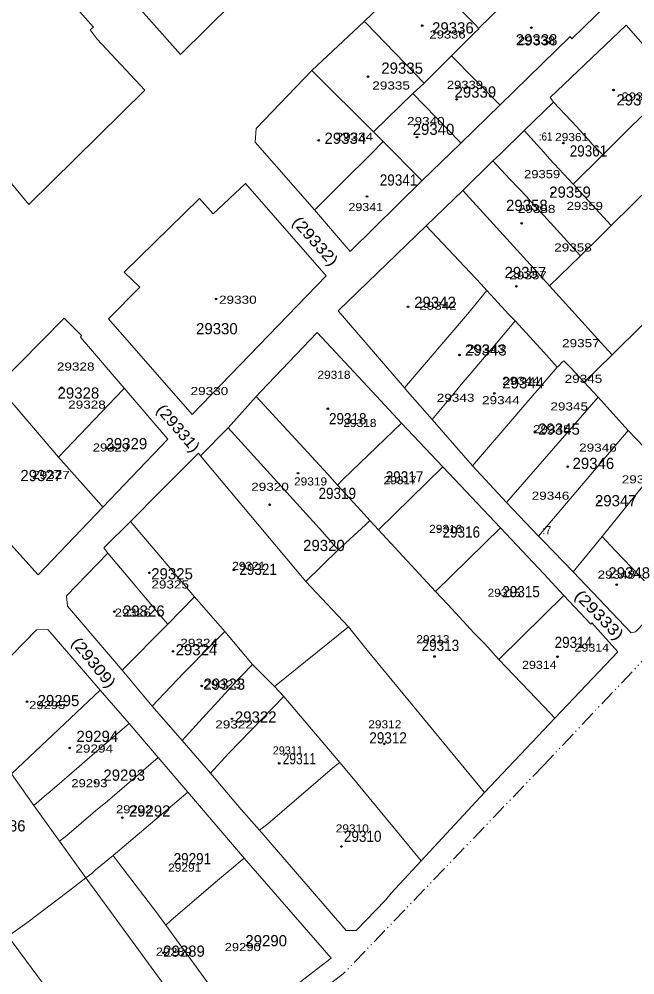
# Model space of a CAD drawing. Extents: x 650553 to 652508, y 239277 to 241647.
# Drawn here: x 650831.5 to 651029.3, y 239562.7 to 239869.5 of the extents above; entities that cross this region are included whole.
import ezdxf

# ---------------------------------------------------------------- set-up
doc = ezdxf.new("R2010")
doc.units = 0
doc.header["$PDMODE"] = 32
doc.header["$PDSIZE"] = 0.5
doc.linetypes.add('DASH_DOUBLE_DOT', pattern=[9.2, 5, -1.2, 0.3, -1.2, 0.3, -1.2])
for name, color, linetype in [('19', 7, 'Continuous'), ('20', 7, 'Continuous'), ('6', 7, 'Continuous')]:
    doc.layers.add(name, color=color, linetype=linetype)
for name, color, linetype, lineweight in [('3', 7, 'Continuous', 13), ('5', 7, 'Continuous', 13), ('52', 7, 'DASH_DOUBLE_DOT', 13)]:
    doc.layers.add(name, color=color, linetype=linetype, lineweight=lineweight)

msp = doc.modelspace()

# ---------------------------------------------------------------- linework, layer by layer
at = {"layer": '3'}
for p, q in [((650879.03, 239720.07), (650877, 239718.08)), ((650949.15, 239586.69), (650951.05, 239588.9))]:
    msp.add_line(p, q, dxfattribs=at)
for points in [[(650908.41, 239883.02), (650883.34, 239858.18), (650864.77, 239879.28), (650855.55, 239889.77), (650845.58, 239901.42), (650836.36, 239911.69), (650810.07, 239942.07), (650801.92, 239951.45), (650792.87, 239961.83), (650784.09, 239971.6), (650771.89, 239986.02)], [(650758.53, 239902.67), (650765.192, 239907.872), (650764.516, 239908.49), (650788.613, 239929.179), (650789.086, 239928.488), (650795.35, 239933.7), (650797.42, 239931.11), (650799.14, 239932.39), (650804.99, 239925.16), (650803.46, 239923.73), (650817.53, 239907.6), (650818.21, 239908.05), (650821.441, 239904.446), (650826.146, 239908.699), (650835.897, 239897.399), (650830.96, 239893.24), (650834.46, 239889.42), (650833.85, 239888.76), (650847.66, 239872.31), (650849.29, 239873.74), (650855.37, 239866.92), (650854.34, 239866.07), (650856.61, 239863.11), (650871.916, 239846.694)], [(650926.38, 239808.25), (650907.36, 239830.06), (650907.67, 239834.39), (650925.58, 239852.98), (650942.36, 239868.78), (650960.13, 239885.88), (650986.44, 239912.2)], [(650758.53, 239902.67), (650760.73, 239900.19), (650759.19, 239898.72), (650765.32, 239891.73), (650766.99, 239892.99), (650780.49, 239876.39), (650779.94, 239875.79), (650783.12, 239871.78), (650778.188, 239867.604), (650787.995, 239856.292), (650792.37, 239860.72), (650795.54, 239856.63), (650796.29, 239857.11), (650810.17, 239840.72), (650808.48, 239839.35), (650814.17, 239832.2), (650815.19, 239833.07), (650817.72, 239830.34), (650834.635, 239810.007), (650871.916, 239846.694)], [(651004.77, 239891.58), (651020.46, 239874.33), (651009.06, 239863.21), (651008.47, 239863.96), (650986.02, 239841.96), (650973.43, 239829.74), (650960.91, 239817.58), (650937.89, 239794.94), (650926.38, 239808.25)], [(651000, 239839.83), (651003.18, 239842.9), (651002.08, 239844.3), (651026.48, 239867.54), (651042.7, 239849.13), (651054.6, 239835.68), (651074.89, 239813.04), (651087.13, 239799.56), (651095.02, 239790.72), (651117.9, 239765.17), (651103.31, 239750)], [(651000, 239839.83), (650993.74, 239833.78), (650985.86, 239826.07), (650983.65, 239824.03), (650974, 239814.51), (650962.27, 239803.17), (650934.01, 239775.82)], [(650887.09, 239742.6), (650860.21, 239773.29), (650870.256, 239783.469), (650865.276, 239788.29), (650889.499, 239811.936), (650893.871, 239806.992), (650904.24, 239816.76)], [(650904.24, 239816.76), (650930.11, 239787.09), (650887.09, 239742.6)], [(650934.01, 239775.82), (650955.34, 239751.1), (650956.3, 239750)], [(650824.49, 239751.82), (650845.96, 239773.46), (650851.58, 239767.89), (650851.19, 239767.43), (650865.28, 239751.04), (650879.32, 239734.62), (650858.42, 239712.84)], [(650909.2, 239750), (650927.26, 239768.94), (650944.87, 239750)], [(650909.2, 239750), (650907.66, 239748.38), (650898.71, 239738.31), (650889.76, 239729.33), (650889.14, 239730.16), (650879.03, 239720.07)], [(650944.87, 239750), (650954.33, 239739.84), (650967.57, 239725.8), (650986.1, 239706.21), (651000, 239691.42)], [(650956.3, 239750), (650964.17, 239740.93), (650977.18, 239726.11), (650988.08, 239714.35), (650998.38, 239703.47), (651000, 239701.81)], [(651000, 239701.81), (651009.47, 239692.08), (651028.09, 239672.47), (651029.48, 239672.78), (651038.83, 239682.45), (651058.85, 239703.52), (651067.38, 239712.72), (651077.17, 239722.24), (651096.93, 239743.36), (651103.31, 239750)], [(650858.42, 239712.84), (650837.68, 239691.06), (650802.53, 239729.93)], [(650877, 239718.08), (650867.3, 239708.18), (650858.75, 239699.74), (650860.04, 239698.11), (650846.76, 239684.39), (650847.07, 239681), (650864.66, 239660.49), (650874.22, 239648.99), (650883.85, 239637.97), (650893, 239627.41), (650902.79, 239615.77), (650908.76, 239609.09), (650936.55, 239576.94), (650939.8, 239576.9), (650949.15, 239586.69)], [(651000, 239691.42), (651006.48, 239684.52), (651015.11, 239675.28), (651015.45, 239675.69), (651023.78, 239666.38), (651003.54, 239645.12), (651000, 239641.38)], [(650766.66, 239555.85), (650762.69, 239561.36), (650746.99, 239583.49), (650766.57, 239599.63), (650765.87, 239600.32), (650777.65, 239613.61), (650778.65, 239612.38), (650790.25, 239624.22), (650813.28, 239649.12), (650837.06, 239673.5), (650840.71, 239673.57), (650857.5, 239654.04), (650866.83, 239643.35), (650876.22, 239632.41), (650885.67, 239621.34), (650903.75, 239600.18), (650931.7, 239568.01), (650902.59, 239545.65), (650893.39, 239538.45), (650868.88, 239519.76), (650843.34, 239500)], [(650951.05, 239588.9), (650960.64, 239599.28), (650980.94, 239621.22), (651000, 239641.38)]]:
    msp.add_lwpolyline(points, dxfattribs=at)
at = {"layer": '5'}
for p, q in [((650993.74, 239833.78), (651000, 239826.77)), ((651009.43, 239816.56), (651018.95, 239825.92)), ((650974, 239814.51), (651000, 239785.87)), ((651000, 239806.45), (651011.83, 239793.51)), ((651000, 239762.54), (651004.33, 239757.8)), ((650971.69, 239750), (650964.17, 239740.93)), ((650988.08, 239714.35), (651017.51, 239748.19)), ((650998.38, 239703.47), (651027.12, 239737.39)), ((650967.57, 239725.8), (650946.94, 239705.52)), ((650986.1, 239706.21), (650965.25, 239685.71)), ((651000, 239678.11), (651006.48, 239684.52)), ((650985.64, 239663.92), (651000, 239678.11)), ((650937.33, 239674.4), (650913.52, 239655.26)), ((650857.5, 239654.04), (650829.08, 239627.18)), ((651000, 239648.84), (651003.54, 239645.12))]:
    msp.add_line(p, q, dxfattribs=at)
for points in [[(651000, 239886.91), (650979.43, 239866.78), (650979.19, 239866.43), (650977.59, 239864.89), (650976.17, 239863.49), (650970.39, 239857.73), (650961.58, 239849), (650957.95, 239845.67), (650945.33, 239833.29)], [(650960.13, 239885.88), (650960.617, 239885.38), (650968.98, 239876.79), (650975.37, 239870.37), (650978.06, 239867.64), (650979.19, 239866.43)], [(650942.36, 239868.78), (650942.846, 239868.28), (650961.58, 239849)], [(650970.39, 239857.73), (650985.524, 239842.46), (650986.02, 239841.96)], [(650925.58, 239852.98), (650926.08, 239852.482), (650945.33, 239833.29), (650948.48, 239830.21)], [(651003.18, 239842.9), (651010.69, 239834.98), (651015.18, 239829.88), (651015.37, 239829.53), (651018.95, 239825.92), (651028.04, 239834.93), (651033.56, 239840.23), (651042.7, 239849.13)], [(650957.95, 239845.67), (650972.944, 239830.24), (650973.43, 239829.74)], [(651001.83, 239783.86), (651011.83, 239793.51), (651018.25, 239799.79), (651021.7, 239803.27), (651054.6, 239835.68)], [(650948.48, 239830.21), (650944.86, 239826.59), (650935.08, 239816.87)], [(650948.48, 239830.21), (650960.418, 239818.08), (650960.91, 239817.58)], [(651000, 239826.77), (651001.89, 239824.65), (651009.43, 239816.56), (651021.7, 239803.27)], [(650983.65, 239824.03), (650989.15, 239818.18), (650994.73, 239812.37), (650994.92, 239812.08), (650999.38, 239807.13), (651000, 239806.45)], [(650935.08, 239816.87), (650926.88, 239808.745), (650926.38, 239808.25)], [(651012.96, 239753.01), (651021.99, 239761.78), (651031.72, 239771.33), (651041.21, 239780.58), (651044.83, 239784.08), (651056.34, 239795.18), (651074.89, 239813.04)], [(650962.27, 239803.17), (650979.93, 239784.39), (650981.77, 239782.39), (650988.83, 239774.73), (650990.79, 239772.63), (651000, 239762.54)], [(651000, 239785.87), (651001.83, 239783.86), (651018.46, 239765.63), (651021.99, 239761.78)], [(650981.77, 239782.39), (650975.54, 239774.82), (650955.34, 239751.1)], [(650990.79, 239772.63), (650987.18, 239768.25), (650972.99, 239751.57), (650971.69, 239750)], [(650977.18, 239726.11), (651004.33, 239757.8), (651004.79, 239758.09), (651005.89, 239759.37), (651006.43, 239759.78), (651008.62, 239757.67), (651010.07, 239756.03), (651012.96, 239753.01), (651017.51, 239748.19)], [(650844.2, 239728.86), (650824.919, 239751.32), (650824.49, 239751.82)], [(650844.2, 239728.86), (650864.805, 239750.54), (650865.28, 239751.04)], [(650907.66, 239748.38), (650930.51, 239723.55), (650933.82, 239719.91), (650941.35, 239711.65), (650944.16, 239708.52), (650946.94, 239705.52), (650965.25, 239685.71), (650969.21, 239681.6), (650972.94, 239677.51), (650977.6, 239672.48), (650981.14, 239668.9), (650985.64, 239663.92), (651000, 239648.84)], [(651017.51, 239748.19), (651027.12, 239737.39), (651037.52, 239726.58), (651047.83, 239715.28), (651048.66, 239714.26), (651058.85, 239703.52)], [(650954.33, 239739.84), (650935.56, 239721.82), (650933.82, 239719.91)], [(650898.71, 239738.31), (650906.99, 239729.11), (650928.98, 239704.86), (650934.02, 239699.13)], [(650889.76, 239729.33), (650923.6, 239688.94), (650937.33, 239674.4), (650943.35, 239666.93), (650980.94, 239621.22)], [(650858.42, 239712.84), (650857.976, 239713.34), (650844.2, 239728.86)], [(651009.47, 239692.08), (651018.73, 239703.44), (651037.52, 239726.58)], [(650867.3, 239708.18), (650887.84, 239684.08), (650897.6, 239672.88), (650906.43, 239662.37), (650913.52, 239655.26), (650916.57, 239652.08), (650920.1, 239647.88), (650934.57, 239630.89), (650938.37, 239626.21), (650960.64, 239599.28)], [(650944.16, 239708.52), (650942.82, 239707.12), (650934.02, 239699.13), (650923.6, 239688.94)], [(651018.73, 239703.44), (651022.99, 239698.95), (651030.9, 239690.63), (651038.83, 239682.45)], [(650860.04, 239698.11), (650868.14, 239688.4), (650871.4, 239684.6), (650875.07, 239680.21), (650875.43, 239679.63), (650879.28, 239675.29)], [(650887.84, 239684.08), (650879.28, 239675.29), (650864.66, 239660.49)], [(650897.6, 239672.88), (650893.41, 239668.7), (650884.29, 239659.56), (650874.22, 239648.99)], [(650906.43, 239662.37), (650903.06, 239658.75), (650902.1, 239657.84), (650894.24, 239649.27), (650892.67, 239647.51), (650883.85, 239637.97)], [(650916.57, 239652.08), (650898.9, 239633.9), (650893, 239627.41)], [(650813.28, 239649.12), (650825.35, 239632.21), (650829.08, 239627.18), (650836.27, 239617.04), (650844.45, 239605.56), (650852.96, 239593.81), (650855.66, 239590.17), (650893.39, 239538.45)], [(650866.83, 239643.35), (650855.79, 239633.96), (650848.35, 239627.48), (650841.4, 239621.49), (650840.3, 239620.6), (650836.27, 239617.04)], [(650876.22, 239632.41), (650859.94, 239618.43), (650856.01, 239615.3), (650846.81, 239607.47), (650844.45, 239605.56)], [(650934.57, 239630.89), (650932.96, 239629.65), (650911.41, 239611.17), (650908.76, 239609.09)], [(650790.25, 239624.22), (650808.99, 239600.06), (650816.68, 239590.35), (650822.43, 239582.83), (650823.49, 239581.14), (650828, 239575.1), (650829.56, 239572.82), (650868.88, 239519.76)], [(650885.67, 239621.34), (650861.68, 239601.04), (650856.01, 239596.37), (650854.86, 239595.27), (650852.96, 239593.81), (650847.23, 239589.49), (650833.94, 239579.39), (650828, 239575.1)], [(650861.68, 239601.04), (650864.89, 239596.76), (650875.8, 239582.61), (650878.61, 239578.67), (650894.41, 239557), (650895.06, 239556.01), (650902.59, 239545.65)], [(650903.75, 239600.18), (650894.55, 239592.44), (650880.27, 239580.13), (650878.61, 239578.67)]]:
    msp.add_lwpolyline(points, dxfattribs=at)
at = {"layer": '52'}
for points in [[(651113.762, 239749.917), (651060.054, 239693.394), (650999.992, 239629.999)], [(650999.992, 239629.999), (650935.614, 239563.008), (650853.248, 239499.982)]]:
    msp.add_lwpolyline(points, dxfattribs=at)
at = {"layer": '6'}
for p in [(650960.954, 239867.44), (650996.066, 239866.77), (650943.567, 239851.035), (651022.433, 239846.73), (650972.045, 239843.735), (650927.733, 239830.615), (650959.315, 239831.625), (651006.309, 239829.73), (650943.283, 239812.575), (651002.813, 239813.645), (650992.941, 239803.945), (650991.215, 239783.76), (650894.731, 239779.68), (650956.407, 239777.135), (650972.953, 239761.66), (650845.117, 239751.16), (650984.138, 239749.37), (650930.68, 239744.425), (650997.2, 239737.065), (650861.938, 239731.94), (650921.084, 239723.755), (651007.695, 239725.83), (650950.426, 239722.68), (651017.913, 239714.735), (650911.975, 239713.625), (650966.408, 239705.755), (650900.463, 239692.71), (650873.337, 239691.735), (651023.44, 239687.955), (650985.92, 239685.065), (650862.125, 239679.3), (650880.941, 239666.535), (650964.913, 239664.87), (651004.423, 239664.82), (650890.118, 239655.425), (650834.063, 239650.375), (650899.915, 239644.89), (650847.787, 239635.54), (650948.799, 239636.84), (650915.03, 239630.585), (650855.898, 239624.455), (650864.69, 239613.11), (650935.037, 239603.895), (650882.999, 239600.005), (650905.122, 239572.915), (650877.839, 239569.745)]:
    msp.add_point(p, dxfattribs=at)

# ---------------------------------------------------------------- texts
at = {"layer": '19'}
for s, p in [('29336', (650964.153, 239864.905)), ('29338', (650991.026, 239861.074)), ('29335', (650947.838, 239851.975)), ('29339', (650971.351, 239844.314)), ('29362', (651023.361, 239841.807)), ('29340', (650957.914, 239832.342)), ('29334', (650929.601, 239829.469)), ('29359', (651001.763, 239812.171)), ('29358', (650987.906, 239807.922)), ('29357', (650987.426, 239786.373)), ('29342', (650958.395, 239776.794)), ('29330', (650888.338, 239768.328)), ('29343', (650974.71, 239761.471)), ('29344', (650986.706, 239750.936)), ('29328', (650843.859, 239747.673)), ('29345', (650998.224, 239736.091)), ('29329', (650859.273, 239731.413)), ('29346', (651009.262, 239725.078)), ('29327', (650831.917, 239721.185)), ('29347', (651016.46, 239713.106)), ('29320', (650922.728, 239698.741)), ('29325', (650873.939, 239689.643)), ('29348', (651020.779, 239689.937)), ('29326', (650864.863, 239677.687)), ('29324', (650881.771, 239665.262)), ('29323', (650890.735, 239654.207)), ('29295', (650837.466, 239648.94)), ('29322', (650900.812, 239643.672)), ('29294', (650849.943, 239637.447)), ('29293', (650858.581, 239624.997)), ('29292', (650866.738, 239613.504)), ('29286', (650820.191, 239608.716)), ('29290', (650904.169, 239571.843)), ('29289', (650877.776, 239568.491))]:
    msp.add_text(s, height=3.6, dxfattribs=at).set_placement(p)
for s, width, p in [('29361', 0.9, (651008.358, 239825.402)), ('29341', 0.9, (650947.358, 239816.061)), ('29318', 0.9, (650931.043, 239739.444)), ('29317', 0.9, (650949.278, 239720.769)), ('29319', 0.9, (650927.676, 239715.445)), ('29316', 0.9, (650967.513, 239703.051)), ('29321', 0.9, (650902.252, 239691.079)), ('29315', 0.9, (650986.708, 239683.897)), ('29314', 0.9, (651003.503, 239667.615)), ('29313', 0.9, (650960.795, 239666.658)), ('29312', 0.9, (650944, 239636.968)), ('29311', 0.8, (650916.167, 239630.264)), ('29310', 0.9, (650935.841, 239605.363)), ('29291', 0.9, (650881.135, 239598.181))]:
    msp.add_text(s, height=3.6, dxfattribs=dict(at, width=width)).set_placement(p)
for s, rotation, width, p in [('(29332)', 311.724, 1.15, (650918.957, 239804.18)), ('(29331)', 310.614, 1.1, (650875.334, 239743.959)), ('(29333)', 314.179, 1.2, (651009.629, 239684.139)), ('(29309)', 309.181, 1.15, (650848.057, 239669.221))]:
    msp.add_text(s, height=3.6, rotation=rotation, dxfattribs=dict(at, width=width)).set_placement(p)
at = {"layer": '20'}
for s, width, p in [('29336', 1.2, (650963.311, 239863.284)), ('29338', 1.25, (650991.65, 239861.348)), ('29335', 1.25, (650944.95, 239846.902)), ('29339', 1.2, (650968.898, 239847.119)), ('29362', 1.2, (651024.985, 239843.374)), ('29340', 1.25, (650956.108, 239835.476)), ('29334', 1.25, (650933.151, 239830.447)), (':61', 0.9, (650998.444, 239830.523)), ('29361', 1.1, (651003.661, 239830.343)), ('29359', 1.2, (650993.688, 239818.45)), ('29341', 1.15, (650937.294, 239807.89)), ('29358', 1.25, (650991.684, 239807.272)), ('29359', 1.2, (651007.403, 239808.241)), ('29358', 1.25, (651003.367, 239794.9)), ('29357', 1.25, (650988.921, 239785.978)), ('29330', 1.25, (650895.721, 239778.131)), ('29342', 1.25, (650960.01, 239776.202)), ('29357', 1.25, (651005.896, 239764.184)), ('29343', 1.25, (650975.387, 239762.361)), ('29328', 1.25, (650843.647, 239756.671)), ('29318', 1.1, (650927.325, 239754.03)), ('29344', 1.25, (650986.674, 239752.1)), ('29345', 1.25, (651006.726, 239752.737)), ('29330', 1.25, (650886.587, 239748.816)), ('29343', 1.25, (650965.668, 239746.644)), ('29344', 1.25, (650980.204, 239745.882)), ('29328', 1.25, (650847.257, 239744.453)), ('29345', 1.25, (651002.16, 239743.864)), ('29318', 1.1, (650935.655, 239738.557)), ('29345', 1.25, (650996.576, 239736.548)), ('29329', 1.2, (650855.174, 239730.689)), ('29346', 1.25, (651011.386, 239730.649)), ('29327', 1.25, (650835.696, 239721.873)), ('29320', 1.25, (650906.053, 239718.077)), ('29319', 1.1, (650919.807, 239719.791)), ('29317', 1.1, (650948.56, 239720.174)), ('29347', 1.25, (651025.068, 239720.458)), ('29346', 1.25, (650996.14, 239715.211)), ('29316', 1.1, (650963.214, 239704.553)), ('29321', 1.1, (650899.949, 239692.678)), ('29348', 1.25, (651017.294, 239689.884)), ('29325', 1.25, (650873.995, 239686.722)), ('29315', 1.1, (650981.984, 239684.049)), ('29326', 1.2, (650862.223, 239677.673)), ('29313', 1.1, (650959.094, 239669.137)), ('29324', 1.25, (650883.305, 239667.971)), ('29314', 1.15, (651009.89, 239666.442)), ('29314', 1.15, (650993.047, 239660.903)), ('29323', 1.25, (650890.68, 239654.636)), ('29295', 1.2, (650834.733, 239648.002)), ('29322', 1.25, (650894.507, 239641.777)), ('29312', 1.1, (650943.651, 239641.816)), ('29294', 1.25, (650849.597, 239634.029)), ('29293', 1.2, (650848.288, 239622.914)), ('29292', 1.2, (650862.631, 239614.539)), ('29310', 1.1, (650933.206, 239608.383)), ('29291', 1.1, (650879.378, 239595.81)), ('29290', 1.2, (650897.535, 239570.292)), ('29289', 1.2, (650875.403, 239568.811))]:
    msp.add_text(s, height=2.6, dxfattribs=dict(at, width=width)).set_placement(p)
for s, p in [(':7', (650999.532, 239704.146)), ('29311', (650912.983, 239633.434))]:
    msp.add_text(s, height=2.6, dxfattribs=at).set_placement(p)

doc.saveas('drawing.dxf')
